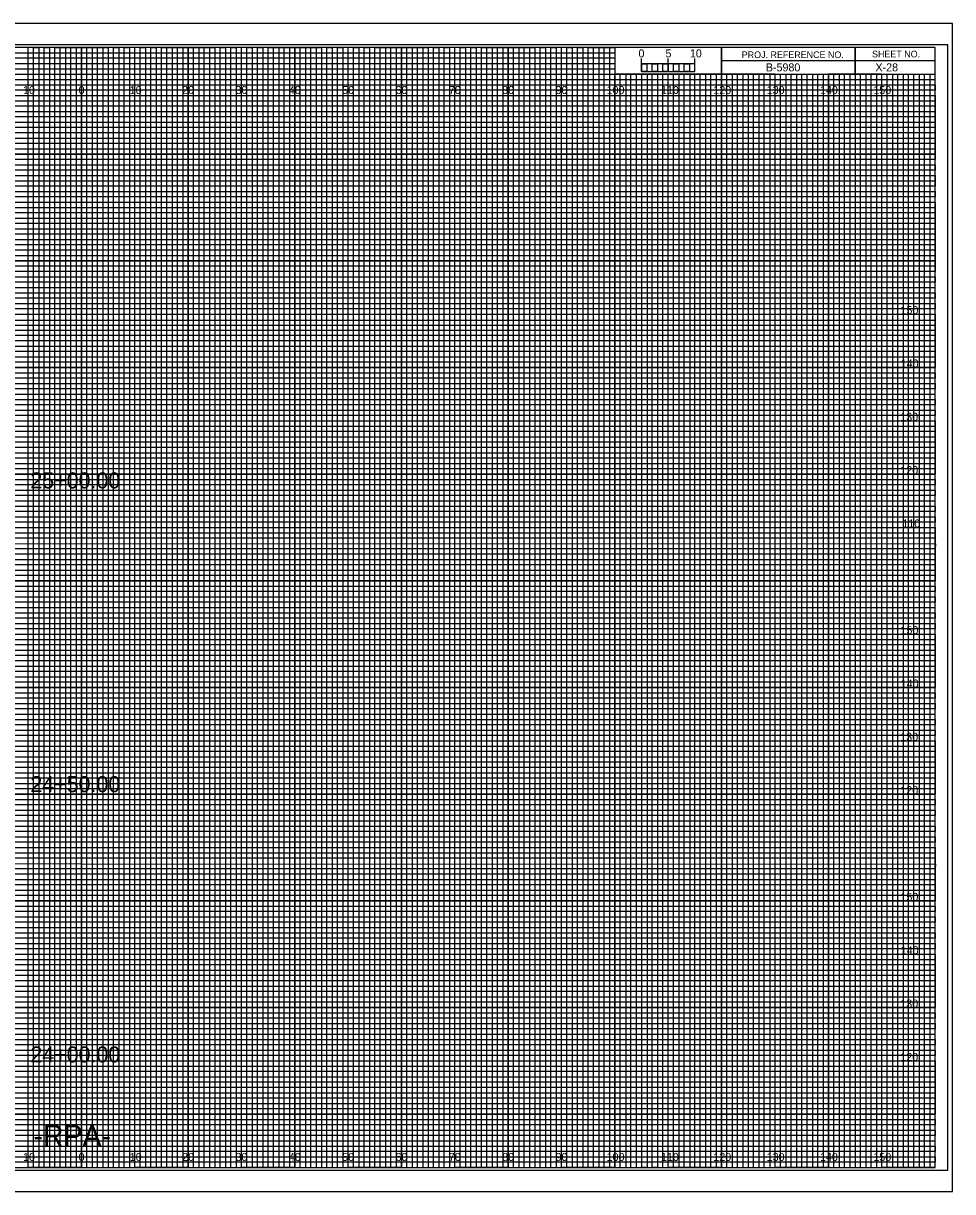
# Model space of a CAD drawing. Extents: x -13 to 323, y -5 to 1974.
# Drawn here: x 149.1 to 323.3, y 875.5 to 1094.5 of the extents above; entities that cross this region are included whole.
import ezdxf

# ---------------------------------------------------------------- set-up
doc = ezdxf.new("R2010")
doc.units = 0
for name, color, linetype in [('Exist Cross Section Cell', 7, 'Continuous'), ('Exist XS Center Line Elevation Label', 7, 'Continuous'), ('Exist XS Ground Line', 7, 'Continuous'), ('Prop CMT Bridge Girder Bottom Critical Point Inside', 7, 'Continuous'), ('Prop CMT Guardrail Graphics', 7, 'Continuous'), ('Prop CMT Guardrail Widen Shoulder', 7, 'Continuous'), ('Prop CMT Pvmt Course 1', 7, 'Continuous'), ('Prop CMT Pvmt Course 2', 7, 'Continuous'), ('Prop CMT Pvmt Course 3', 7, 'Continuous'), ('Prop CMT Pvmt Surface', 7, 'Continuous'), ('Prop CMT Pvmt Surface Shoulder', 7, 'Continuous'), ('Prop CMT Shld Paved Course 1', 7, 'Continuous'), ('Prop CMT Shld Paved Course 2', 7, 'Continuous'), ('Prop CMT Shld Paved Course 3', 7, 'Continuous'), ('Prop CMT Slope Grass', 7, 'Continuous'), ('Prop CMT Subgrade Earthwork', 7, 'Continuous'), ('Scratch_Level_1', 7, 'Continuous')]:
    doc.layers.add(name, color=color, linetype=linetype)

msp = doc.modelspace()

# ---------------------------------------------------------------- linework, layer by layer
at = {"layer": 'Exist XS Center Line Elevation Label'}
for points in [[(145, 880), (155, 880), (155, 1090), (165, 1090), (165, 880), (175, 880), (175, 1090), (185, 1090), (185, 880), (195, 880), (195, 1090), (205, 1090), (205, 880), (215, 880), (215, 1090), (225, 1090), (225, 880), (235, 880), (235, 1090), (245, 1090), (245, 880), (255, 880), (255, 1090), (259.93, 1090), (260, 1090), (260, 1085), (264.99, 1085), (264.99, 880), (275, 880), (275, 1085), (285, 1085), (285, 880), (295, 880), (295, 1085), (305, 1085), (305, 880), (315, 880), (315, 1085)], [(0, 1085), (275, 1085)], [(0, 1065), (320, 1065), (320, 1075), (0, 1075)], [(0, 1045), (320, 1045), (320, 1055), (0, 1055)], [(0, 1025), (320, 1025), (320, 1035), (0, 1035)], [(0, 1005), (320, 1005), (320, 1015), (0, 1015)], [(0, 985), (320, 985), (320, 995), (0, 995)], [(0, 965), (320, 965), (320, 975), (0, 975)], [(0, 945), (320, 945), (320, 955), (0, 955)], [(0, 925), (320, 925), (320, 935), (0, 935)], [(0, 905), (320, 905), (320, 915), (0, 915)], [(0, 885), (320, 885), (320, 895), (0, 895)]]:
    msp.add_lwpolyline(points, dxfattribs=at)
at = {"layer": 'Exist XS Ground Line'}
for p, q in [((150, 1090), (140, 1090)), ((150, 880), (150, 1090)), ((170, 1090), (160, 1090)), ((160, 1090), (160, 880)), ((170, 880), (170, 1090)), ((190, 1090), (180, 1090)), ((180, 1090), (180, 880)), ((190, 880), (190, 1090)), ((210, 1090), (200, 1090)), ((200, 1090), (200, 880)), ((210, 880), (210, 1090)), ((230, 1090), (220, 1090)), ((220, 1090), (220, 880)), ((230, 880), (230, 1090)), ((250, 1090), (240, 1090)), ((240, 1090), (240, 880)), ((250, 880), (250, 1090)), ((260, 1090), (260, 880)), ((270, 880), (270, 1085)), ((290, 1085), (280, 1085)), ((280, 1085), (280, 880)), ((290, 880), (290, 1085)), ((310, 1085), (300, 1085)), ((300, 1085), (300, 880)), ((310, 880), (310, 1085)), ((160, 880), (150, 880)), ((180, 880), (170, 880)), ((200, 880), (190, 880)), ((220, 880), (210, 880)), ((240, 880), (230, 880)), ((260, 880), (250, 880)), ((280, 880), (270, 880)), ((300, 880), (290, 880)), ((320, 880), (310, 880)), ((320, 880), (320, 880))]:
    msp.add_line(p, q, dxfattribs=at)
for points in [[(0, 1080), (320, 1080), (320, 1070), (0, 1070)], [(0, 1060), (320, 1060), (320, 1050), (0, 1050)], [(0, 1040), (320, 1040), (320, 1030), (0, 1030)], [(0, 1020), (320, 1020), (320, 1010), (0, 1010)], [(0, 1000), (320, 1000), (320, 990), (0, 990)], [(0, 980), (320, 980), (320, 970), (0, 970)], [(0, 960), (320, 960), (320, 950), (0, 950)], [(0, 940), (320, 940), (320, 930), (0, 930)], [(0, 920), (320, 920), (320, 910), (0, 910)], [(0, 900), (320, 900), (320, 890), (0, 890)]]:
    msp.add_lwpolyline(points, dxfattribs=at)
at = {"layer": 'Prop CMT Pvmt Course 2'}
for p, q in [((265, 1085.49), (265, 1087.9)), ((265, 1086.9), (265, 1087.9)), ((270, 1085.49), (270, 1087.9)), ((275, 1085.49), (275, 1087.9)), ((275, 1086.9), (275, 1087.9))]:
    msp.add_line(p, q, dxfattribs=at)
for points in [[(275, 1086.9), (265, 1086.9), (265, 1085.49), (275, 1085.49)], [(265, 1086.9), (266, 1086.9), (266, 1085.49), (265, 1085.49)], [(267, 1086.9), (268, 1086.9), (268, 1085.49), (267, 1085.49)], [(269, 1086.9), (270, 1086.9), (270, 1085.49), (269, 1085.49)], [(271, 1086.9), (272, 1086.9), (272, 1085.49), (271, 1085.49)], [(273, 1086.9), (274, 1086.9), (274, 1085.49), (273, 1085.49)]]:
    msp.add_lwpolyline(points, close=True, dxfattribs=at)
at = {"layer": 'Prop CMT Pvmt Course 3'}
msp.add_lwpolyline([(-13.4, 875.5), (323.3, 875.5), (323.3, 1094.5), (-13.4, 1094.5)], close=True, dxfattribs=at)
at = {"layer": 'Prop CMT Pvmt Surface'}
for p, q in [((150, 880), (150, 1090)), ((160, 880), (160, 1090)), ((170, 880), (170, 1090)), ((180, 880), (180, 1090)), ((190, 880), (190, 1090)), ((200, 880), (200, 1090)), ((210, 880), (210, 1090)), ((220, 880), (220, 1090)), ((230, 880), (230, 1090)), ((240, 880), (240, 1090)), ((250, 880), (250, 1090)), ((260, 880), (260, 1084.69)), ((270, 880), (270, 1084.69)), ((280, 880), (280, 1084.69)), ((290, 880), (290, 1084.69)), ((300, 880), (300, 1084.69)), ((310, 880), (310, 1084.69)), ((0, 1080), (320, 1080)), ((0, 1070), (320, 1070)), ((0, 1060), (320, 1060)), ((0, 1050), (320, 1050)), ((0, 1040), (320, 1040)), ((0, 1030), (320, 1030)), ((0, 1020), (320, 1020)), ((0, 1010), (320, 1010)), ((0, 1000), (320, 1000)), ((0, 990), (320, 990)), ((0, 980), (320, 980)), ((0, 970), (320, 970)), ((0, 960), (320, 960)), ((0, 950), (320, 950)), ((0, 940), (320, 940)), ((0, 930), (320, 930)), ((0, 920), (320, 920)), ((0, 910), (320, 910)), ((0, 900), (320, 900)), ((0, 890), (320, 890))]:
    msp.add_line(p, q, dxfattribs=at)
at = {"layer": 'Prop CMT Pvmt Surface Shoulder'}
for p, q in [((323.3, 1094.5), (-13.4, 1094.5)), ((-13.4, 875.5), (323.3, 875.5))]:
    msp.add_line(p, q, dxfattribs=at)
at = {"layer": 'Prop CMT Shld Paved Course 1'}
for p, q in [((0, 1089), (260, 1089)), ((260, 1089), (260, 1087.98)), ((260, 1087.98), (0, 1087.98)), ((0, 1087), (260, 1087)), ((260, 1087), (260, 1085.89)), ((260, 1085.89), (0, 1085.89)), ((0, 1084), (320, 1084))]:
    msp.add_line(p, q, dxfattribs=at)
for points in [[(0, 1083), (270, 1083), (320, 1083), (320, 1082), (0, 1082)], [(0, 1081), (320, 1081), (320, 1079), (0, 1079)], [(0, 1078), (320, 1078), (320, 1077), (0, 1076.98)], [(0, 1076), (320, 1076), (320, 1074), (0, 1074)], [(0, 1073), (320, 1073), (320, 1072), (0, 1072)], [(0, 1071), (320, 1071), (320, 1069), (0, 1069)], [(0, 1068), (320, 1068), (320, 1067), (0, 1067)], [(0, 1066), (320, 1066), (320, 1064), (0, 1064)], [(0, 1063), (320, 1063), (320, 1062), (0, 1062)], [(0, 1061), (320, 1061), (320, 1059), (0, 1059)], [(0, 1058), (320, 1058), (320, 1057), (0, 1057)], [(0, 1056), (320, 1056), (320, 1053.95), (320, 1053), (320, 1052), (0, 1052)], [(0, 1054), (320, 1054), (320, 1053), (0, 1053)], [(0, 1051), (320, 1051), (320, 1049), (0, 1049.03)], [(0, 1049.03), (320, 1049), (320, 1048), (0, 1048)], [(0, 1047), (320, 1047), (320, 1046), (0, 1046)], [(0, 1044), (320, 1044), (320, 1043), (0, 1043)], [(0, 1042), (320, 1042), (320, 1041), (0, 1041)], [(-0.07, 1038.89), (320, 1038.89), (320, 1037.88), (-0.07, 1037.88)], [(0, 1037), (320, 1037), (320, 1036), (0, 1036)], [(0, 1034), (320, 1034), (320, 1033), (0, 1033)], [(0, 1032), (320, 1032), (320, 1031), (0, 1031)], [(0, 1029), (320, 1029), (320, 1028), (0, 1028)], [(0, 1027), (320, 1027), (320, 1026), (0, 1026)], [(0, 1024), (320, 1024), (320, 1023), (0, 1023)], [(0, 1022), (320, 1022), (320, 1021), (0, 1021)], [(0, 1019), (320, 1019), (319.99, 1017.98), (0, 1018)], [(0, 1017), (320, 1017), (320, 1016), (0, 1016)], [(0, 1014), (320, 1014), (320, 1013), (0, 1013)], [(0, 1012), (320, 1012), (320, 1011), (0, 1011)], [(0, 1009), (320, 1009), (320, 1008), (0, 1008)], [(0, 1007), (320, 1007), (320, 1006), (0, 1006)], [(0, 1004), (320, 1004), (320, 1003), (0, 1003)], [(0, 1002), (320, 1002), (320, 1001), (0, 1001)], [(0, 999), (320, 999), (320, 998), (0, 998)], [(0, 996.99), (320.07, 996.91), (320, 996), (0, 996)], [(0, 994), (320, 994), (320, 993), (0, 993)], [(0, 992), (320, 992), (320, 991), (0, 991)], [(0, 989), (320, 989), (320, 988), (0, 988)], [(0, 987), (320, 987), (320, 986), (0, 986)], [(0, 984), (320, 984), (320, 983), (0, 983)], [(0, 982), (320, 982), (320, 981), (0, 981)], [(0, 979), (320, 979), (320, 978), (0, 978)], [(0, 977), (320, 977), (320, 976), (0, 976)], [(0, 974), (320, 974), (320, 973), (0, 973)], [(0, 972), (320, 972), (320, 971), (0, 971)], [(0, 969), (320, 969), (320, 968), (0, 968)], [(0, 967), (320, 967), (320, 966), (0, 966)], [(0, 964), (320, 964), (320, 963), (0, 963)], [(0, 962), (320, 962), (320, 961), (0, 961)], [(0, 959), (320, 959), (319.99, 957.98), (0, 958)], [(0, 957), (320, 957), (320, 956), (0, 956)], [(0, 954), (320, 954), (320, 953), (0, 953)], [(0, 952), (320, 952), (320, 951), (0, 951)], [(0, 949), (320, 949), (320, 948), (0, 948)], [(0, 947), (320, 947), (320, 946), (0, 946)], [(0, 944), (320, 944), (320, 943), (0, 943)], [(0, 942), (320, 942), (320, 941), (0, 941)], [(0, 939), (320, 939), (320, 938), (0, 938)], [(0, 936.99), (320.07, 936.91), (320, 936), (0, 936)], [(0, 934), (320, 934), (320, 933), (0, 933)], [(0, 932), (320, 932), (320, 931), (0, 931)], [(0, 929), (320, 929), (320, 928), (0, 928)], [(0, 927), (320, 927), (320, 926), (0, 926)], [(0, 924), (320, 924), (320, 923), (0, 923)], [(0, 922), (320, 922), (320, 921), (0, 921)], [(0, 919), (320, 919), (320, 918), (0, 918)], [(0, 917), (320, 917), (320, 916), (0, 916)], [(0, 914), (320, 914), (320, 913), (0, 913)], [(0, 912), (320, 912), (320, 911), (0, 911)], [(0, 909), (320, 909), (320, 908), (0, 908)], [(0, 907), (320, 907), (320, 906), (0, 906)], [(0, 904), (320, 904), (320, 903), (0, 903)], [(0, 902), (320, 902), (320, 901), (0, 901)], [(0, 899), (320, 899), (320, 898), (0, 898)], [(0, 897), (320, 897), (320, 896), (0, 896)], [(0, 894), (320, 894), (320, 893), (0, 893)], [(0, 892), (320, 892), (320, 891), (0, 891)], [(0, 889), (320, 889), (320, 888), (0, 888)], [(0, 887), (320, 887), (320, 886), (0, 886)], [(0, 884), (320, 884), (320, 883), (0, 883)], [(0, 882), (320, 882), (320, 881), (0, 881)]]:
    msp.add_lwpolyline(points, dxfattribs=at)
at = {"layer": 'Prop CMT Shld Paved Course 2'}
for p, q in [((305, 1090), (305, 1085)), ((305, 1085), (305, 1090)), ((280, 1087.5), (280, 1085)), ((320, 1087.49), (280, 1087.49)), ((280, 1085), (320, 1085))]:
    msp.add_line(p, q, dxfattribs=at)
for points in [[(320, 1090), (0, 1090), (0, 880), (320, 880)], [(280, 1090), (260, 1090), (260, 1085.03), (280, 1085.03)], [(320, 1090), (280, 1090), (280, 1085), (320, 1085)]]:
    msp.add_lwpolyline(points, close=True, dxfattribs=at)
at = {"layer": 'Prop CMT Shld Paved Course 3'}
for p, q in [((267, 1085), (266.01, 1085)), ((266.01, 1085), (266.01, 880)), ((267, 880), (267, 1085)), ((269, 1085), (268, 1085)), ((268, 1085), (268, 880)), ((269, 880), (269, 1085)), ((266.01, 880), (265, 880)), ((268, 880), (267, 880))]:
    msp.add_line(p, q, dxfattribs=at)
for points in [[(150, 880), (151, 880), (151, 1090), (152, 1090), (152, 880)], [(152, 880), (153, 880), (153, 1090), (154, 1090), (154, 880)], [(155, 880), (156, 880), (156, 1090), (157, 1090), (157, 880)], [(157, 880), (158, 880), (158, 1090), (159, 1090), (159, 880)], [(160, 880), (161, 880), (161, 1090), (162, 1090), (162, 880)], [(162, 880), (163, 880), (163, 1090), (164, 1090), (164, 880)], [(165, 880), (166, 880), (166, 1090), (167, 1090), (167, 880)], [(167, 880), (168, 880), (168, 1090), (169, 1090), (169, 880)], [(170, 880), (171, 880), (171, 1090), (172, 1090), (172, 880)], [(172, 880), (173, 880), (173, 1090), (174, 1090), (174, 880)], [(175, 880), (176, 880), (176, 1090), (177, 1090), (177, 880)], [(177, 880), (178, 880), (178, 1090), (179, 1090), (179, 880)], [(180, 880), (181, 880), (181, 1090), (182, 1090), (182, 880)], [(182, 880), (183, 880), (183, 1090), (184, 1090), (184, 880)], [(185, 880), (186, 880), (186, 1090), (187, 1090), (187, 880)], [(187, 880), (188, 880), (188, 1090), (189, 1090), (189, 880)], [(190, 880), (191, 880), (191, 1090), (192, 1090), (192, 880)], [(192, 880), (193, 880), (193, 1090), (194, 1090), (194, 880)], [(195, 880), (196, 880), (196, 1090), (197, 1090), (197, 880)], [(197, 880), (198, 880), (198, 1090), (199, 1090), (199, 880)], [(200, 880), (201, 880), (201, 1090), (202, 1090), (202, 880)], [(202, 880), (203, 880), (203, 1090), (204, 1090), (204, 880)], [(205, 880), (206, 880), (206, 1090), (207, 1090), (207, 880)], [(207, 880), (208, 880), (208, 1090), (209, 1090), (209, 880)], [(210, 880), (211, 880), (211, 1090), (212, 1090), (212, 880)], [(212, 880), (213, 880), (213, 1090), (214, 1090), (214, 880)], [(215, 880), (216, 880), (216, 1090), (217, 1090), (217, 880)], [(217, 880), (218, 880), (218, 1090), (219, 1090), (219, 880)], [(220, 880), (221, 880), (221, 1090), (222, 1090), (222, 880)], [(222, 880), (223, 880), (223, 1090), (224, 1090), (224, 880)], [(225, 880), (226, 880), (226, 1090), (227, 1090), (227, 880)], [(227, 880), (228, 880), (228, 1090), (229, 1090), (229, 880)], [(230, 880), (231, 880), (231, 1090), (232, 1090), (232, 880)], [(232, 880), (233, 880), (233, 1090), (234, 1090), (234, 880)], [(235, 880), (236, 880), (236, 1090), (237, 1090), (237, 880)], [(237, 880), (238, 880), (238, 1090), (239, 1090), (239, 880)], [(240, 880), (241, 880), (241, 1090), (242, 1090), (242, 880)], [(242, 880), (243, 880), (243, 1090), (244, 1090), (244, 880)], [(245, 880), (246, 880), (246, 1090), (247, 1090), (247, 880)], [(247, 880), (248, 880), (248, 1090), (249, 1090), (249, 880)], [(250, 880), (251, 880), (251, 1090), (252, 1090), (252, 880)], [(252, 880), (253, 880), (253, 1090), (254, 1090), (254, 880)], [(255, 880), (256, 880), (256, 1090), (257, 1090), (257, 880)], [(257, 880), (258, 880), (258, 1090), (259, 1090), (259, 880)], [(260, 880), (261, 880), (261, 1085), (262.02, 1085), (262.02, 880)], [(262, 880), (263, 880), (263, 1085), (263.99, 1085), (263.99, 880)], [(270, 880), (270.98, 880), (270.98, 1085), (272, 1085), (272, 880)], [(272, 880), (273, 880), (273, 1085), (274.05, 1085), (274.05, 880)], [(275, 880), (276, 880), (276, 1085), (277, 1085), (277, 880)], [(277, 880), (278, 880), (278, 1085), (279, 1085), (279, 880)], [(280, 880), (281, 880), (281, 1085), (282, 1085), (282, 880)], [(282, 880), (283, 880), (283, 1085), (284, 1085), (284, 880)], [(285, 880), (286, 880), (286, 1085), (287, 1085), (287, 880)], [(287, 880), (288, 880), (288, 1085), (289, 1085), (289, 880)], [(290, 880), (291, 880), (291, 1085), (292, 1085), (292, 880)], [(292, 880), (293, 880), (293, 1085), (294, 1085), (294, 880)], [(295, 880), (296, 880), (296, 1085), (297, 1085), (297, 880)], [(297, 880), (298, 880), (298, 1085), (299, 1085), (299, 880)], [(300, 880), (301, 880), (301, 1085), (302, 1085), (302, 880)], [(302, 880), (303, 880), (303, 1085), (304, 1085), (304, 880)], [(305, 880), (306, 880), (306, 1085), (307, 1085), (307, 880)], [(307, 880), (308, 880), (308, 1085), (309, 1085), (309, 880)], [(310, 880), (311, 880), (311, 1085), (312, 1085), (312, 880)], [(312, 880), (313, 880), (313, 1085), (314, 1085), (314, 880)], [(315, 880), (316, 880), (316, 1085), (317, 1085), (317, 880)], [(317, 880), (318, 880), (318, 1085), (319, 1085), (319, 880)]]:
    msp.add_lwpolyline(points, dxfattribs=at)
at = {"layer": 'Prop CMT Subgrade Earthwork'}
msp.add_lwpolyline([(-10.8, 879.5), (322.4, 879.5), (322.4, 1090.5), (-10.8, 1090.5)], close=True, dxfattribs=at)

# ---------------------------------------------------------------- texts
at = {"layer": 'Exist Cross Section Cell'}
for s, p in [('10', (149.04, 1081.25)), ('0', (159.45, 1081.25)), ('0', (159.45, 1081.25)), ('10', (169.04, 1081.25)), ('20', (178.86, 1081.25)), ('30', (188.86, 1081.25)), ('40', (198.86, 1081.25)), ('50', (208.86, 1081.25)), ('60', (218.86, 1081.25)), ('70', (228.86, 1081.25)), ('80', (238.86, 1081.25)), ('90', (248.86, 1081.25)), ('100', (258.44, 1081.25)), ('110', (268.62, 1081.25)), ('120', (278.44, 1081.25)), ('130', (288.44, 1081.25)), ('140', (298.44, 1081.25)), ('150', (308.44, 1081.25)), ('10', (149.04, 881.25)), ('0', (159.45, 881.25)), ('0', (159.45, 881.25)), ('10', (169.04, 881.25)), ('20', (178.86, 881.25)), ('30', (188.86, 881.25)), ('40', (198.86, 881.25)), ('50', (208.86, 881.25)), ('60', (218.86, 881.25)), ('70', (228.86, 881.25)), ('80', (238.86, 881.25)), ('90', (248.86, 881.25)), ('100', (258.44, 881.25)), ('110', (268.62, 881.25)), ('120', (278.44, 881.25)), ('130', (288.44, 881.25)), ('140', (298.44, 881.25)), ('150', (308.44, 881.25))]:
    msp.add_text(s, height=1.5, dxfattribs=at).set_placement(p)
at = {"layer": 'Prop CMT Bridge Girder Bottom Critical Point Inside'}
for s, p in [('5', (269.47, 1088.12)), ('10', (274.04, 1088.12))]:
    msp.add_text(s, height=1.5, dxfattribs=at).set_placement(p)
at = {"layer": 'Prop CMT Guardrail Graphics'}
msp.add_text('B-5980', height=1.5, dxfattribs=at).set_placement((288.28, 1085.5))
at = {"layer": 'Prop CMT Guardrail Widen Shoulder'}
msp.add_text('X-28', height=1.5, dxfattribs=at).set_placement((308.83, 1085.5))
at = {"layer": 'Prop CMT Pvmt Course 1'}
for s, p in [('150', (313.52, 1040)), ('140', (313.57, 1030)), ('130', (313.49, 1020)), ('120', (313.5, 1010)), ('110', (313.88, 1000)), ('150', (313.52, 980)), ('140', (313.57, 970)), ('130', (313.49, 960)), ('120', (313.5, 950)), ('150', (313.52, 930)), ('140', (313.57, 920)), ('130', (313.49, 910)), ('120', (313.5, 900))]:
    msp.add_text(s, height=1.5, dxfattribs=at).set_placement(p)
at = {"layer": 'Prop CMT Pvmt Course 2'}
msp.add_text('0', height=1.5, dxfattribs=at).set_placement((264.41, 1088.12))
at = {"layer": 'Prop CMT Shld Paved Course 2'}
for s, p in [('PROJ. REFERENCE NO.', (283.77, 1087.99)), ('SHEET NO.', (308.19, 1088.12))]:
    msp.add_text(s, height=1.25, dxfattribs=at).set_placement(p)
at = {"layer": 'Prop CMT Slope Grass'}
for s, p in [('25+00.00', (150.41, 1007.33)), ('24+50.00', (150.41, 950.39)), ('24+00.00', (150.41, 899.72))]:
    msp.add_text(s, height=3, dxfattribs=at).set_placement(p)
at = {"layer": 'Scratch_Level_1'}
msp.add_text('-RPA-', height=4, dxfattribs=at).set_placement((150.97, 884))

doc.saveas('drawing.dxf')
